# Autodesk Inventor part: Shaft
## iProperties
Shininess: 77.0
Length Units: 11269
Angle Units: 11279
Time Units: 11290
Mass Units: 11283
Length Display Precision: 3
Angle Display Precision: 2
Created: 2002-01
Part Number: Shaft
Document SubType Name: Modeling
Designer: ***
Density: 0.0
Volumn: 0.0
Area: 0.0
PropertySet Name: Model Information
Control State: 0
Master: False
Checked Out: False
Author: ***
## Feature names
1. Revolution1
2. Extrusion1
3. Extrusion2
4. Hole1
5. Chamfer1
